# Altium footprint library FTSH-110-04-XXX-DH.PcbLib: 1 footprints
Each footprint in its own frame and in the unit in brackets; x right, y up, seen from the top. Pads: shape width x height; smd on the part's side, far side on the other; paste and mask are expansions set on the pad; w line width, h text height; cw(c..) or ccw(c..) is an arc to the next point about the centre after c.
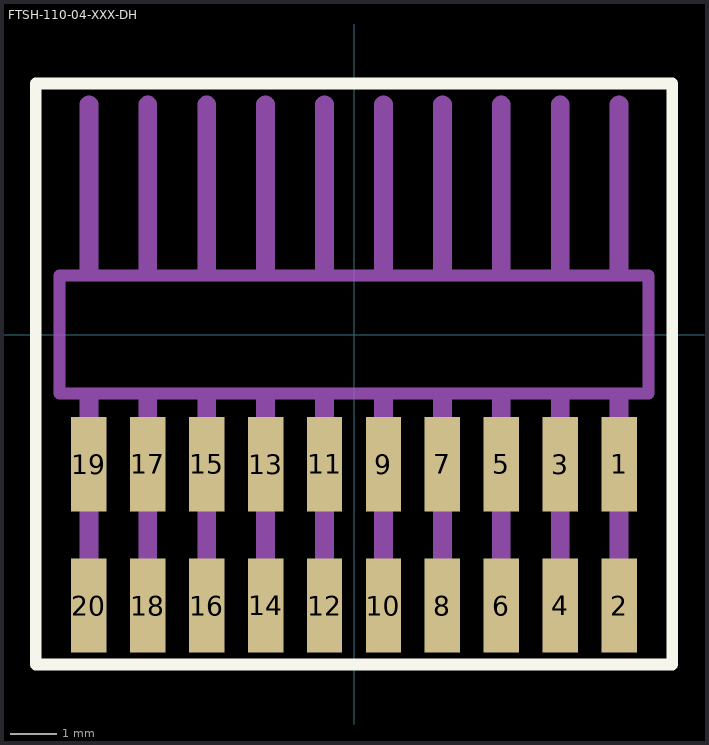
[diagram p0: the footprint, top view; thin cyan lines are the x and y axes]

## FTSH-110-04-XXX-DH [mil]
pads (20):
  rect 30x80 smd mask+2: 1(225,-110) 2(225,-230) 3(175,-110) 4(175,-230) 5(125,-110) 6(125,-230) 7(75,-110) 8(75,-230) 9(25,-110) 10(25,-230) 11(-25,-110) 12(-25,-230) 13(-75,-110) 14(-75,-230) 15(-125,-110) 16(-125,-230) 17(-175,-110) 18(-175,-230) 19(-225,-110) 20(-225,-230)
Top Overlay:
  lines w10: -270,-280 270,-280 270,213 -270,213 -270,-280
Mechanical 1:
  lines w10: -250,-50 250,-50 250,50 -250,50 -250,-50
  lines w16: -225,-250 -225,-55 ; -225,55 -225,195 ; -175,-250 -175,-55 ; -175,55 -175,195 ; -125,-250 -125,-55 ; -125,55 -125,195 ; -75,-250 -75,-55 ; -75,55 -75,195 ; -25,-250 -25,-55 ; -25,55 -25,195 ; 25,-250 25,-55 ; 25,55 25,195 ; 75,-250 75,-55 ; 75,55 75,195 ; 125,-250 125,-55 ; 125,55 125,195 ; 175,-250 175,-55 ; 175,55 175,195 ; 225,-250 225,-55 ; 225,55 225,195
  text "J1" at -17.57,-18 h30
